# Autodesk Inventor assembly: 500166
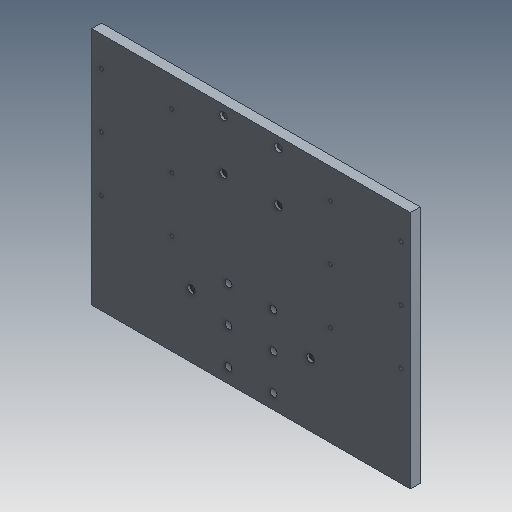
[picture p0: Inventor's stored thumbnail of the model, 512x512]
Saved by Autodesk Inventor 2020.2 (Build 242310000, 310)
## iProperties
Created: 2000-01
Part Number: 500166
Description: PLT-XX,SA,CP,05,160,120,PLATE,TRANSFER
Document SubType Name: Assembly
Designer: sspink
Mass: 4179.32 g
Surface Area: 2767.53 cm^2
Volume: 1534.69 cm^3
Density: 2.72324 g/cm^3
Control State: 0
Checked Out: False
Master: False
Shininess: 0.0
Length Units: 11272
Angle Units: 11279
Time Units: 11290
Mass Units: 11286
Length Display Precision: 3
Angle Display Precision: 2
Compacted: True
Dimensions: 12x0,5x16 in
Mass: 9,214 lb
DocNumber: 500166.iam
Folder: 01 - Themengebiete\Simplification\01 - Packaging machine\
VDS_Category: 3D Komponenten
Density: 0.0
Volumn: 0.0
Area: 0.0
PropertySet Name: Model Information
Author: sspink
Revision Number: -
Title: 500166
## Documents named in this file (4)
- D:\07 - DEMODATEN\OTX 2019 - Dataset - UPDATE - Dez2019\Designs\07-Packing machine\500166.iam
- D:\07 - DEMODATEN\OTX 2019 - Dataset - UPDATE - Dez2019\Designs\07-Packing machine\Parts\ADSK-011290.ipt
- D:\07 - DEMODATEN\OTX 2019 - Dataset - UPDATE - Dez2019\Designs\07-Packing machine\Parts\ADSK-011736.ipt
- D:\07 - DEMODATEN\OTX 2019 - Dataset - UPDATE - Dez2019\Designs\07-Packing machine\Parts\ADSK-011735.ipt
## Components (19 placed, 3 different names)
1. ADSK-011290:1 — Einfügen:1, Einfügen:2, Einfügen:3, Einfügen:4, Einfügen:5, Einfügen:6, Einfügen:7, Einfügen:8, Einfügen:9, Einfügen:10, Einfügen:11, Einfügen:12, Einfügen:13, Einfügen:14, Einfügen:15, Einfügen:16, Einfügen:17, Einfügen:18
2. ADSK-011736:1 — Einfügen:14
3. ADSK-011736:2 — Einfügen:13
4. ADSK-011736:3 — Einfügen:15
5. ADSK-011736:4 — Einfügen:16
6. ADSK-011736:5 — Einfügen:17
7. ADSK-011736:6 — Einfügen:18
8. ADSK-011735:2 — Einfügen:10
9. ADSK-011735:3 — Einfügen:7
10. ADSK-011735:4 — Einfügen:8
11. ADSK-011735:5 — Einfügen:9
12. ADSK-011735:6 — Einfügen:12
13. ADSK-011735:7 — Einfügen:11
14. ADSK-011735:8 — Einfügen:2
15. ADSK-011735:9 — Einfügen:1
16. ADSK-011735:10 — Einfügen:4
17. ADSK-011735:11 — Einfügen:3
18. ADSK-011735:12 — Einfügen:5
19. ADSK-011735:13 — Einfügen:6
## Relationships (18: Insert 18)
- Einfügen:1 [Insert]: ADSK-011290:1 ↔ ADSK-011735:9
- Einfügen:2 [Insert]: ADSK-011290:1 ↔ ADSK-011735:8
- Einfügen:3 [Insert]: ADSK-011290:1 ↔ ADSK-011735:11
- Einfügen:4 [Insert]: ADSK-011290:1 ↔ ADSK-011735:10
- Einfügen:5 [Insert]: ADSK-011290:1 ↔ ADSK-011735:12
- Einfügen:6 [Insert]: ADSK-011290:1 ↔ ADSK-011735:13
- Einfügen:7 [Insert]: ADSK-011290:1 ↔ ADSK-011735:3
- Einfügen:8 [Insert]: ADSK-011290:1 ↔ ADSK-011735:4
- Einfügen:9 [Insert]: ADSK-011290:1 ↔ ADSK-011735:5
- Einfügen:10 [Insert]: ADSK-011290:1 ↔ ADSK-011735:2
- Einfügen:11 [Insert]: ADSK-011290:1 ↔ ADSK-011735:7
- Einfügen:12 [Insert]: ADSK-011290:1 ↔ ADSK-011735:6
- Einfügen:13 [Insert]: ADSK-011290:1 ↔ ADSK-011736:2
- Einfügen:14 [Insert]: ADSK-011290:1 ↔ ADSK-011736:1
- Einfügen:15 [Insert]: ADSK-011290:1 ↔ ADSK-011736:3
- Einfügen:16 [Insert]: ADSK-011290:1 ↔ ADSK-011736:4
- Einfügen:17 [Insert]: ADSK-011290:1 ↔ ADSK-011736:5
- Einfügen:18 [Insert]: ADSK-011290:1 ↔ ADSK-011736:6
